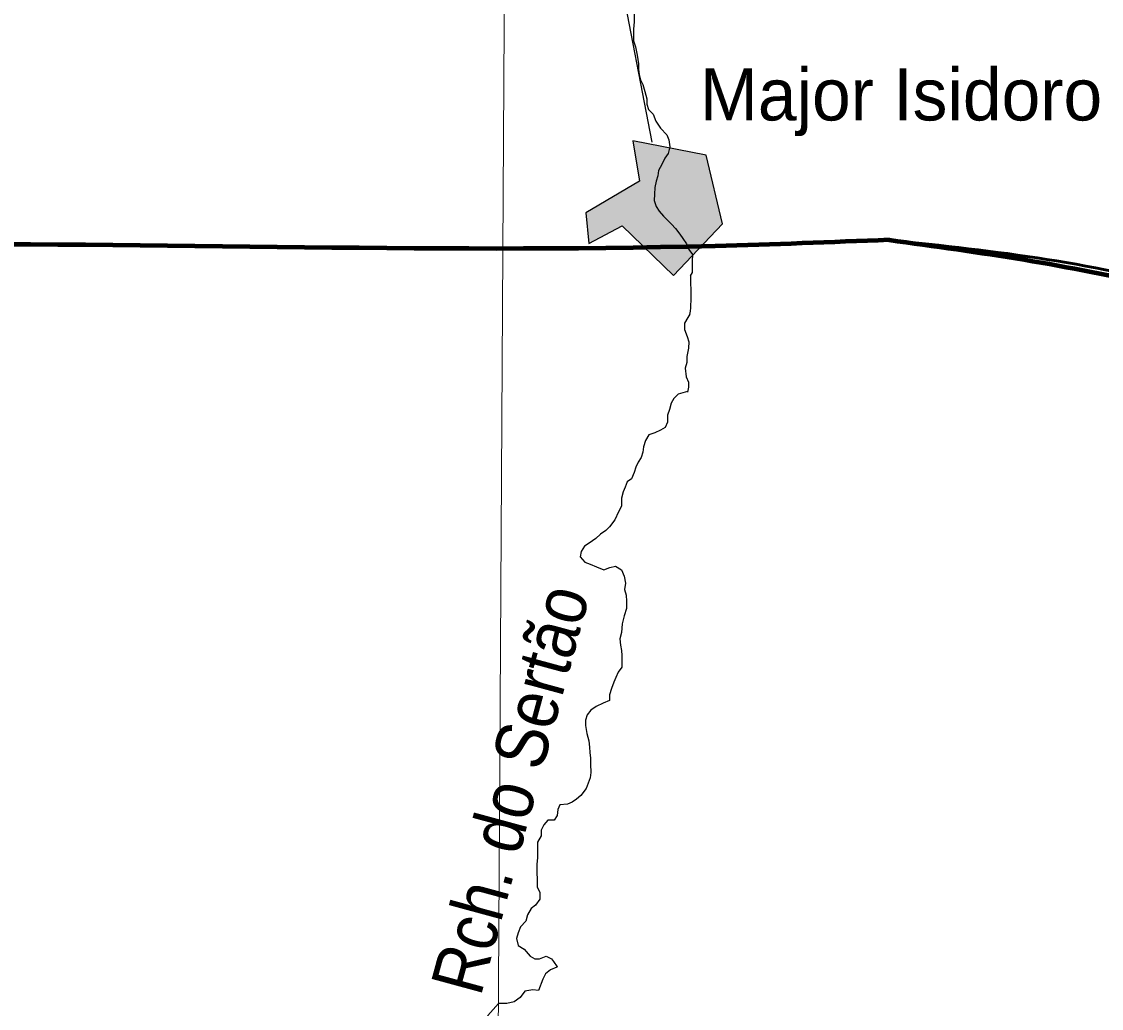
# Model space of a CAD drawing. Extents: x -1643653 to 4543381, y 1624270 to 13878484.
# Drawn here: x 714916 to 725287, y 8938163 to 8947643 of the extents above; entities that cross this region are included whole.
import ezdxf
from ezdxf.enums import TextEntityAlignment as Align

# ---------------------------------------------------------------- set-up
doc = ezdxf.new("R2010")
doc.units = 0
doc.header["$LTSCALE"] = 200
for name, color, linetype, lineweight in [('1', 7, 'Continuous', 13), ('12', 7, 'Continuous', 25), ('21', 7, 'Continuous', 25), ('24', 7, 'Continuous', 25), ('26', 7, 'Continuous', 106), ('28', 7, 'Continuous', 53), ('60', 7, 'Continuous', 13)]:
    doc.layers.add(name, color=color, linetype=linetype, lineweight=lineweight)
doc.layers.add('41', color=7, linetype='Continuous')
doc.layers.add('49', color=7, linetype='Continuous')

msp = doc.modelspace()

# ---------------------------------------------------------------- hatches: boundary and pattern name
at = {"layer": '21'}
msp.add_hatch(color=256, dxfattribs=at).paths.add_polyline_path([(720787.1, 8946496.4), (720850.6, 8946110.2), (720334.5, 8945806.5), (720363, 8945511.1), (720684.9, 8945680.2), (721175.9, 8945203.6), (721647.6, 8945700.8), (721491.5, 8946358.8)])

# ---------------------------------------------------------------- linework, layer by layer
at = {"layer": '1'}
msp.add_lwpolyline([(719978.9, 9023574.5), (719561.6, 8949232.2), (719215.6, 8890710.6)], dxfattribs=at)
at = {"layer": '12'}
msp.add_lwpolyline([(720797.8, 8949224.2), (720675.5, 8948838), (720637.7, 8948242.1), (720657.5, 8948094.3), (720969.8, 8946485.6)], dxfattribs=at)
at = {"layer": '21'}
msp.add_lwpolyline([(720787.1, 8946496.4), (720850.6, 8946110.2), (720334.5, 8945806.5), (720363, 8945511.1), (720684.9, 8945680.2), (721175.9, 8945203.6), (721647.6, 8945700.8), (721491.5, 8946358.8)], close=True, dxfattribs=at)
at = {"layer": '24'}
for points in [[(720799.5, 8947747.6), (720798.7, 8947640.7), (720793.1, 8947569.4), (720792.8, 8947518.5), (720792.4, 8947457.4), (720812.3, 8947401.2), (720827, 8947319.7), (720841.7, 8947238.1), (720841.4, 8947187.2), (720846.1, 8947136.2), (720861, 8947085.2), (720881, 8947039.2), (720900.9, 8946972.9), (720920.8, 8946901.5), (720920.4, 8946850.6), (720935.3, 8946799.6), (720980.8, 8946753.5), (721005.7, 8946687.1), (721051.1, 8946620.6), (721111.6, 8946554.1), (721131.6, 8946508.1), (721141.3, 8946441.8), (721125.6, 8946375.7), (721094.8, 8946330.1), (721063.9, 8946269.2), (721033, 8946213.3), (721027.5, 8946162.4), (721011.9, 8946111.6), (720996.2, 8946050.6), (720995.8, 8945984.4), (720990.3, 8945923.3), (721010.2, 8945867.2), (721040.4, 8945821.2), (721080.8, 8945775.1), (721116.2, 8945739.2), (721156.6, 8945698.2), (721197, 8945657.3), (721237.2, 8945601), (721267.5, 8945560.1)], [(721267.5, 8945560.1), (721302.7, 8945508.9), (721322.7, 8945452.8), (721358, 8945406.8), (721357.6, 8945345.6), (721357.2, 8945289.6), (721356.8, 8945233.6), (721336.6, 8945202.4)], [(721333.1, 8944831.8), (721314, 8944802.2), (721283.1, 8944746.3), (721282.7, 8944685.2), (721307.7, 8944618.9), (721322.6, 8944567.9), (721322.1, 8944506.8), (721306.3, 8944425.4), (721305.9, 8944369.4), (721290.3, 8944313.4), (721299.9, 8944231.9), (721319.9, 8944180.8), (721319.5, 8944129.9), (721309.9, 8944083.2)], [(721311.4, 8944090.8), (721222.4, 8944064.3), (721181.5, 8944023.8), (721155.7, 8943978.2), (721140.1, 8943917.2), (721119.3, 8943861.3), (721118.9, 8943795.1), (721098.2, 8943744.3), (721052.2, 8943719.1), (720996.1, 8943694), (720940, 8943673.9), (720909.1, 8943618.1), (720888.3, 8943557.1), (720882.9, 8943506.2), (720867.3, 8943455.4), (720836.5, 8943409.8), (720815.8, 8943364.1), (720800.2, 8943313.2), (720774.3, 8943252.3), (720733.5, 8943222), (720712.8, 8943171.2), (720692.1, 8943125.5), (720676.4, 8943064.5), (720675.9, 8942988.1), (720650.1, 8942932.2), (720613.9, 8942856.1), (720562.6, 8942790.2), (720526.8, 8942754.7), (720475.7, 8942719.4), (720429.6, 8942678.9), (720368.3, 8942633.5), (720322.3, 8942603.2), (720291.4, 8942552.5), (720280.9, 8942501.6), (720326.3, 8942450.4), (720377, 8942429.8), (720437.9, 8942403.9), (720508.9, 8942378), (720565, 8942398), (720621, 8942413), (720676.7, 8942377), (720701.7, 8942315.7), (720716.5, 8942249.4), (720706, 8942188.4), (720720.8, 8942132.3), (720725.5, 8942076.2), (720725, 8942004.9), (720704.2, 8941933.8), (720683.3, 8941857.5), (720677.7, 8941776.1), (720662, 8941715.1), (720666.7, 8941653.9), (720676.5, 8941602.9), (720681.2, 8941552), (720680.8, 8941501.1), (720680.4, 8941440), (720644.5, 8941394.3), (720623.8, 8941343.6), (720603.2, 8941297.8), (720582.4, 8941236.9), (720561.6, 8941175.9), (720561.2, 8941119.9), (720500, 8941094.8), (720433.7, 8941064.6), (720382.6, 8941029.3), (720346.7, 8940983.7), (720331.1, 8940932.9), (720330.7, 8940881.9), (720345.5, 8940805.5), (720365.3, 8940734), (720370, 8940672.9), (720374.7, 8940621.9), (720379.4, 8940565.9), (720379, 8940509.9), (720383.5, 8940428.4), (720378.1, 8940377.5), (720336.7, 8940275.9), (720285.4, 8940210), (720244.5, 8940174.6), (720203.6, 8940144.3), (720157.6, 8940124.2), (720086.4, 8940119.6), (720065.7, 8940073.9), (720060.3, 8940017.9), (720029.4, 8939972.2), (719968.4, 8939972.6), (719932.5, 8939927), (719906.7, 8939876.2), (719906.3, 8939820.2), (719870.3, 8939759.3), (719869.9, 8939703.3), (719869.3, 8939611.7), (719863.7, 8939545.5), (719863.2, 8939464), (719867.9, 8939408), (719867.3, 8939326.5), (719892.4, 8939280.5), (719892, 8939214.3), (719850.8, 8939153.5), (719810, 8939123.2), (719773.9, 8939062.3)], [(719773.9, 8939062.3), (719758.2, 8939001.2), (719707, 8938945.6), (719686.3, 8938889.7), (719670.6, 8938833.7), (719685.4, 8938767.4), (719741.1, 8938731.5), (719801.7, 8938664.9), (719844, 8938640.7), (719890.2, 8938638.6), (719890.2, 8938638.6)], [(719890.2, 8938638.6), (719953.8, 8938664.2), (720004.3, 8938640.4), (720024.2, 8938614.6), (720058.9, 8938563), (720061.4, 8938559.7)], [(720060.8, 8938559.8), (720055.8, 8938559.8), (719994.6, 8938534.7), (719948.5, 8938494.2), (719922.7, 8938443.5), (719881.3, 8938336.8), (719825.4, 8938342.2), (719749, 8938327.4), (719702.8, 8938266.6), (719646.6, 8938226.2), (719575.3, 8938211.3), (719495.9, 8938211.8)], [(719495.9, 8938211.8), (719394.7, 8938096.4), (719328.4, 8937863.4), (719342.1, 8937802.6), (719401.1, 8937732.2), (719437, 8937644.3), (719483.8, 8937567.5), (719487.5, 8937545.9), (719449.3, 8937492.5), (719434.6, 8937455.6), (719420.2, 8937279.4), (719367.4, 8937201.3), (719297.2, 8937190.5), (719130.2, 8937185.6)]]:
    msp.add_lwpolyline(points, dxfattribs=at)
msp.add_spline([(721338.8, 8945205.7), (721343, 8945051.6), (721343, 8944957), (721332, 8944830.1)], degree=3, dxfattribs=at)
at = {"layer": '26'}
for points in [[(723248, 8945546.2), (721577.7, 8945486.6), (713159.8, 8945495.8), (706613.6, 8945459.1), (705684.5, 8945517.6)], [(723248, 8945546.2), (725829.8, 8945095.5), (727540.4, 8944467.3), (728842.4, 8943529.7), (731836.5, 8938343.4)]]:
    msp.add_spline(points, degree=3, dxfattribs=at)
at = {"layer": '28'}
for points in [[(705684.5, 8945517.6), (706613.6, 8945459.1), (713159.8, 8945495.8), (721577.7, 8945486.6), (723248, 8945546.2)], [(723248, 8945546.2), (726235.5, 8945024.6), (727640.7, 8944409.5), (728987.4, 8943325.7), (729924.3, 8941714.7), (731836.5, 8938343.4)]]:
    msp.add_spline(points, degree=3, dxfattribs=at)
at = {"layer": '60', "lineweight": 25}
msp.add_spline([(814781, 9009175.5), (814787.2, 9009173.4), (814796.9, 9009173.4), (814799.4, 9009172.4), (814805.1, 9009174.5), (814805.6, 9009176.5), (814811.7, 9009179.5), (814811.7, 9009179.5), (814801.5, 9009181), (814790.7, 9009181.5), (814784.1, 9009183.1), (814777.4, 9009185.1), (814778.4, 9009175.5)], degree=3, dxfattribs=at)

# ---------------------------------------------------------------- texts
at = {"layer": '41'}
msp.add_text('Major Isidoro', height=500, dxfattribs=at).set_placement((721429.9, 8946693.7))
at = {"layer": '49', "width": 0.9}
msp.add_text('Rch. do Sertão', height=500, rotation=74.808, dxfattribs=at).set_placement((719849.9, 8940205), align=Align.CENTER)

doc.saveas('drawing.dxf')
